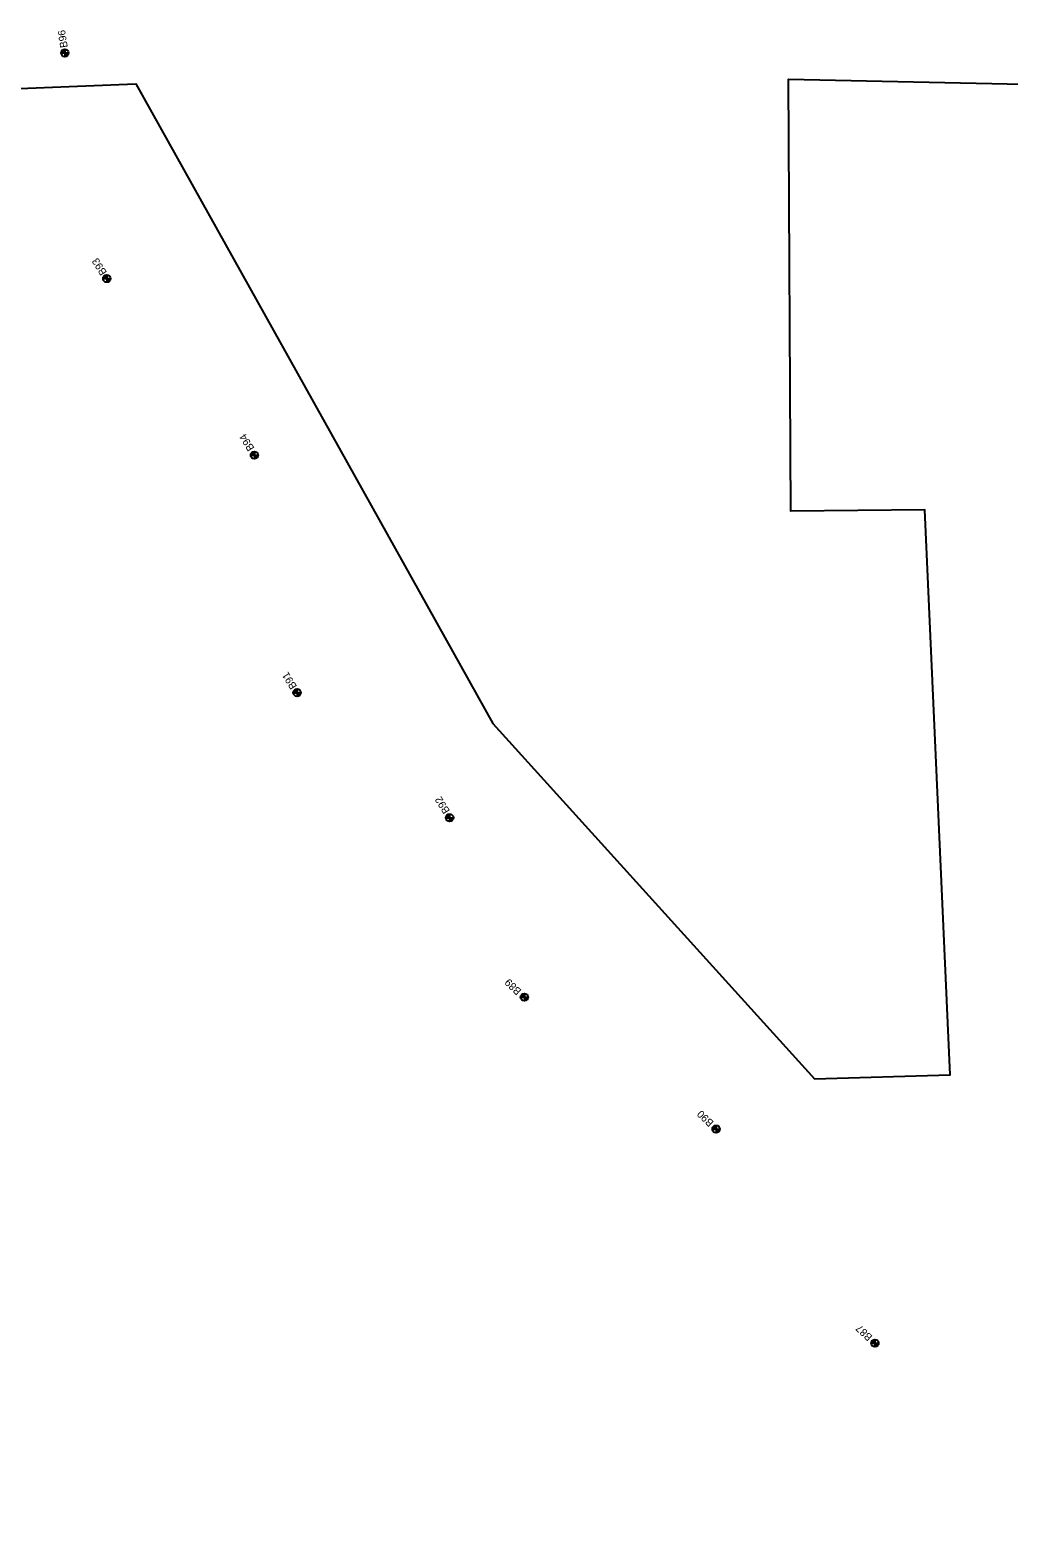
# Model space of a CAD drawing. Extents: x 331323 to 388339, y 121519 to 205315.
# Drawn here: x 356257 to 357560, y 178383 to 180390 of the extents above; entities that cross this region are included whole.
import ezdxf

# ---------------------------------------------------------------- set-up
doc = ezdxf.new("R2010")
doc.units = 0
for name, color, linetype in [('E_SOIL_BORE1 [KAPUR_CADDS_LEVELS]', 7, 'Continuous'), ('E_SOIL_BORE2 [KAPUR_CADDS_LEVELS]', 7, 'Continuous'), ('Level 21', 7, 'Continuous'), ('P_MARK', 7, 'Continuous')]:
    doc.layers.add(name, color=color, linetype=linetype)

msp = doc.modelspace()

# ---------------------------------------------------------------- linework, layer by layer
at = {"layer": 'Level 21'}
msp.add_lwpolyline([(356153.7, 180308.5), (356397.8, 180318.1), (356872.9, 179466.9), (357301.3, 178994.3), (357481.9, 178999.3), (357448.2, 179751.3), (357269.5, 179749.4), (357266.4, 180324.6), (358223.7, 180304), (358222.5, 180067.9), (358788.3, 180072.1), (358818.1, 179129.9), (358711.8, 179133.8), (358705.9, 178944.6), (358813.1, 178940.8), (358862.7, 177251.5)], dxfattribs=at)
at = {"layer": 'P_MARK'}
for p, q in [((356303.3, 180364.4), (356303.3, 180354.4)), ((356298.3, 180359.4), (356308.3, 180359.4)), ((356359.1, 180064.1), (356359.1, 180054.1)), ((356354.1, 180059.1), (356364.1, 180059.1)), ((356550.7, 179824.1), (356560.7, 179824.1)), ((356555.7, 179829.1), (356555.7, 179819.1)), ((356607.4, 179508), (356617.4, 179508)), ((356612.4, 179513), (356612.4, 179503)), ((356810.5, 179341.5), (356820.5, 179341.5)), ((356815.5, 179346.5), (356815.5, 179336.5)), ((356910, 179102.8), (356920, 179102.8)), ((356915, 179107.8), (356915, 179097.8)), ((357165.2, 178927.2), (357175.2, 178927.2)), ((357170.2, 178932.2), (357170.2, 178922.2)), ((357376.6, 178642.3), (357386.6, 178642.3)), ((357381.6, 178647.3), (357381.6, 178637.3))]:
    msp.add_line(p, q, dxfattribs=at)
for centre in [(356303.3, 180359.4), (356359.1, 180059.1), (356555.7, 179824.1), (356612.4, 179508), (356815.5, 179341.5), (356915, 179102.8), (357170.2, 178927.2), (357381.6, 178642.3)]:
    msp.add_circle(centre, 5, dxfattribs=at)
for centre, radius, start, end in [((356303.3, 180359.4), 4.5, 89.9869, 179.9869), ((356303.3, 180359.4), 4, 89.9869, 179.9869), ((356303.3, 180359.4), 3.5, 89.9869, 179.9869), ((356303.3, 180359.4), 3, 89.9869, 179.9869), ((356303.3, 180359.4), 2.5, 89.9869, 179.9869), ((356303.3, 180359.4), 2, 89.9869, 179.9869), ((356303.3, 180359.4), 1.5, 89.9869, 179.9869), ((356303.3, 180359.4), 1, 89.9869, 179.9869), ((356303.3, 180359.4), 0.5, 89.9869, 179.9869), ((356303.3, 180359.4), 4.5, 269.9869, 359.9869), ((356303.3, 180359.4), 4, 269.9869, 359.9869), ((356303.3, 180359.4), 3.5, 269.9869, 359.9869), ((356303.3, 180359.4), 3, 269.9869, 359.9869), ((356303.3, 180359.4), 2.5, 269.9869, 359.9869), ((356303.3, 180359.4), 2, 269.9869, 359.9869), ((356303.3, 180359.4), 1.5, 269.9869, 359.9869), ((356303.3, 180359.4), 1, 269.9869, 359.9869), ((356303.3, 180359.4), 0.5, 269.9869, 359.9869), ((356359.1, 180059.1), 4.5, 89.9869, 179.9869), ((356359.1, 180059.1), 4, 89.9869, 179.9869), ((356359.1, 180059.1), 3.5, 89.9869, 179.9869), ((356359.1, 180059.1), 3, 89.9869, 179.9869), ((356359.1, 180059.1), 2.5, 89.9869, 179.9869), ((356359.1, 180059.1), 2, 89.9869, 179.9869), ((356359.1, 180059.1), 1.5, 89.9869, 179.9869), ((356359.1, 180059.1), 1, 89.9869, 179.9869), ((356359.1, 180059.1), 0.5, 89.9869, 179.9869), ((356359.1, 180059.1), 4.5, 269.9869, 359.9869), ((356359.1, 180059.1), 4, 269.9869, 359.9869), ((356359.1, 180059.1), 3.5, 269.9869, 359.9869), ((356359.1, 180059.1), 3, 269.9869, 359.9869), ((356359.1, 180059.1), 2.5, 269.9869, 359.9869), ((356359.1, 180059.1), 2, 269.9869, 359.9869), ((356359.1, 180059.1), 1.5, 269.9869, 359.9869), ((356359.1, 180059.1), 1, 269.9869, 359.9869), ((356359.1, 180059.1), 0.5, 269.9869, 359.9869), ((356555.7, 179824.1), 4.5, 89.9869, 179.9869), ((356555.7, 179824.1), 4, 89.9869, 179.9869), ((356555.7, 179824.1), 3.5, 89.9869, 179.9869), ((356555.7, 179824.1), 3, 89.9869, 179.9869), ((356555.7, 179824.1), 2.5, 89.9869, 179.9869), ((356555.7, 179824.1), 2, 89.9869, 179.9869), ((356555.7, 179824.1), 1.5, 89.9869, 179.9869), ((356555.7, 179824.1), 1, 89.9869, 179.9869), ((356555.7, 179824.1), 0.5, 89.9869, 179.9869), ((356555.7, 179824.1), 4.5, 269.9869, 359.9869), ((356555.7, 179824.1), 4, 269.9869, 359.9869), ((356555.7, 179824.1), 3.5, 269.9869, 359.9869), ((356555.7, 179824.1), 3, 269.9869, 359.9869), ((356555.7, 179824.1), 2.5, 269.9869, 359.9869), ((356555.7, 179824.1), 2, 269.9869, 359.9869), ((356555.7, 179824.1), 1.5, 269.9869, 359.9869), ((356555.7, 179824.1), 1, 269.9869, 359.9869), ((356555.7, 179824.1), 0.5, 269.9869, 359.9869), ((356612.4, 179508), 4.5, 89.9869, 179.9869), ((356612.4, 179508), 4, 89.9869, 179.9869), ((356612.4, 179508), 3.5, 89.9869, 179.9869), ((356612.4, 179508), 3, 89.9869, 179.9869), ((356612.4, 179508), 2.5, 89.9869, 179.9869), ((356612.4, 179508), 2, 89.9869, 179.9869), ((356612.4, 179508), 1.5, 89.9869, 179.9869), ((356612.4, 179508), 1, 89.9869, 179.9869), ((356612.4, 179508), 0.5, 89.9869, 179.9869), ((356612.4, 179508), 4.5, 269.9869, 359.9869), ((356612.4, 179508), 4, 269.9869, 359.9869), ((356612.4, 179508), 3.5, 269.9869, 359.9869), ((356612.4, 179508), 3, 269.9869, 359.9869), ((356612.4, 179508), 2.5, 269.9869, 359.9869), ((356612.4, 179508), 2, 269.9869, 359.9869), ((356612.4, 179508), 1.5, 269.9869, 359.9869), ((356612.4, 179508), 1, 269.9869, 359.9869), ((356612.4, 179508), 0.5, 269.9869, 359.9869), ((356815.5, 179341.5), 4.5, 89.9869, 179.9869), ((356815.5, 179341.5), 4, 89.9869, 179.9869), ((356815.5, 179341.5), 3.5, 89.9869, 179.9869), ((356815.5, 179341.5), 3, 89.9869, 179.9869), ((356815.5, 179341.5), 2.5, 89.9869, 179.9869), ((356815.5, 179341.5), 2, 89.9869, 179.9869), ((356815.5, 179341.5), 1.5, 89.9869, 179.9869), ((356815.5, 179341.5), 1, 89.9869, 179.9869), ((356815.5, 179341.5), 0.5, 89.9869, 179.9869), ((356815.5, 179341.5), 4.5, 269.9869, 359.9869), ((356815.5, 179341.5), 4, 269.9869, 359.9869), ((356815.5, 179341.5), 3.5, 269.9869, 359.9869), ((356815.5, 179341.5), 3, 269.9869, 359.9869), ((356815.5, 179341.5), 2.5, 269.9869, 359.9869), ((356815.5, 179341.5), 2, 269.9869, 359.9869), ((356815.5, 179341.5), 1.5, 269.9869, 359.9869), ((356815.5, 179341.5), 1, 269.9869, 359.9869), ((356815.5, 179341.5), 0.5, 269.9869, 359.9869), ((356915, 179102.8), 4.5, 89.9869, 179.9869), ((356915, 179102.8), 4, 89.9869, 179.9869), ((356915, 179102.8), 3.5, 89.9869, 179.9869), ((356915, 179102.8), 3, 89.9869, 179.9869), ((356915, 179102.8), 2.5, 89.9869, 179.9869), ((356915, 179102.8), 2, 89.9869, 179.9869), ((356915, 179102.8), 1.5, 89.9869, 179.9869), ((356915, 179102.8), 1, 89.9869, 179.9869), ((356915, 179102.8), 0.5, 89.9869, 179.9869), ((356915, 179102.8), 4.5, 269.9869, 359.9869), ((356915, 179102.8), 4, 269.9869, 359.9869), ((356915, 179102.8), 3.5, 269.9869, 359.9869), ((356915, 179102.8), 3, 269.9869, 359.9869), ((356915, 179102.8), 2.5, 269.9869, 359.9869), ((356915, 179102.8), 2, 269.9869, 359.9869), ((356915, 179102.8), 1.5, 269.9869, 359.9869), ((356915, 179102.8), 1, 269.9869, 359.9869), ((356915, 179102.8), 0.5, 269.9869, 359.9869), ((357170.2, 178927.2), 4.5, 89.9869, 179.9869), ((357170.2, 178927.2), 4, 89.9869, 179.9869), ((357170.2, 178927.2), 3.5, 89.9869, 179.9869), ((357170.2, 178927.2), 3, 89.9869, 179.9869), ((357170.2, 178927.2), 2.5, 89.9869, 179.9869), ((357170.2, 178927.2), 2, 89.9869, 179.9869), ((357170.2, 178927.2), 1.5, 89.9869, 179.9869), ((357170.2, 178927.2), 1, 89.9869, 179.9869), ((357170.2, 178927.2), 0.5, 89.9869, 179.9869), ((357170.2, 178927.2), 4.5, 269.9869, 359.9869), ((357170.2, 178927.2), 4, 269.9869, 359.9869), ((357170.2, 178927.2), 3.5, 269.9869, 359.9869), ((357170.2, 178927.2), 3, 269.9869, 359.9869), ((357170.2, 178927.2), 2.5, 269.9869, 359.9869), ((357170.2, 178927.2), 2, 269.9869, 359.9869), ((357170.2, 178927.2), 1.5, 269.9869, 359.9869), ((357170.2, 178927.2), 1, 269.9869, 359.9869), ((357170.2, 178927.2), 0.5, 269.9869, 359.9869), ((357381.6, 178642.3), 4.5, 89.9869, 179.9869), ((357381.6, 178642.3), 4, 89.9869, 179.9869), ((357381.6, 178642.3), 3.5, 89.9869, 179.9869), ((357381.6, 178642.3), 3, 89.9869, 179.9869), ((357381.6, 178642.3), 2.5, 89.9869, 179.9869), ((357381.6, 178642.3), 2, 89.9869, 179.9869), ((357381.6, 178642.3), 1.5, 89.9869, 179.9869), ((357381.6, 178642.3), 1, 89.9869, 179.9869), ((357381.6, 178642.3), 0.5, 89.9869, 179.9869), ((357381.6, 178642.3), 4.5, 269.9869, 359.9869), ((357381.6, 178642.3), 4, 269.9869, 359.9869), ((357381.6, 178642.3), 3.5, 269.9869, 359.9869), ((357381.6, 178642.3), 3, 269.9869, 359.9869), ((357381.6, 178642.3), 2.5, 269.9869, 359.9869), ((357381.6, 178642.3), 2, 269.9869, 359.9869), ((357381.6, 178642.3), 1.5, 269.9869, 359.9869), ((357381.6, 178642.3), 1, 269.9869, 359.9869), ((357381.6, 178642.3), 0.5, 269.9869, 359.9869)]:
    msp.add_arc(centre, radius, start, end, dxfattribs=at)

# ---------------------------------------------------------------- texts
at = {"layer": 'E_SOIL_BORE1 [KAPUR_CADDS_LEVELS]'}
for s, p in [('B89', (356911.8, 179111.8)), ('B90', (357167.8, 178936.6)), ('B87', (357379.1, 178651.4))]:
    msp.add_text(s, height=10, rotation=136.1942, dxfattribs=at).set_placement(p)
at = {"layer": 'E_SOIL_BORE2 [KAPUR_CADDS_LEVELS]'}
for s, rotation, p in [('B96', 98.957, (356307.2, 180367)), ('B93', 121.7799, (356359.7, 180067.3)), ('B94', 121.7799, (356556, 179833.4)), ('B91', 121.7799, (356612.7, 179516.4)), ('B92', 121.7799, (356816.3, 179350.8))]:
    msp.add_text(s, height=10, rotation=rotation, dxfattribs=at).set_placement(p)

doc.saveas('drawing.dxf')
